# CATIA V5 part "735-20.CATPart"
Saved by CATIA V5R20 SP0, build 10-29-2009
Part number: 735-20
Bounding box of the stored display mesh (mm): x -20 to 20, y -20 to 20, z -23 to 20
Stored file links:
  C:\Users\Utente\Desktop\IO LAVORO\3D X SITO CF\X SITO\735\735-20.CATPart
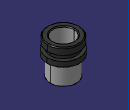
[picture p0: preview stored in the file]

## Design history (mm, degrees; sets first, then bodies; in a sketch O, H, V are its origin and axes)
Set1
  DatumSurface1 to DatumSurface25 "735-20"
Body1 (main body)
